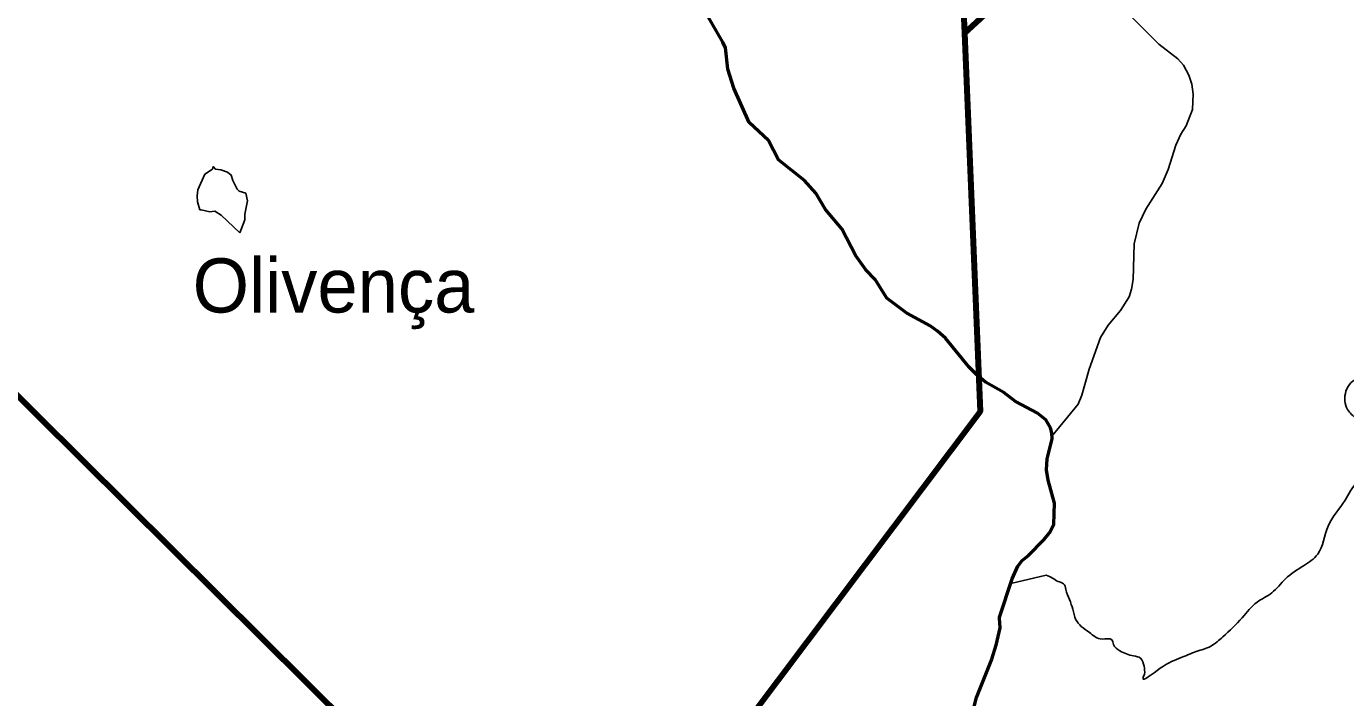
# Model space of a CAD drawing. Extents: x 553962 to 842807, y 8883888 to 9032388.
# Drawn here: x 696848 to 709028, y 8942741 to 8948937 of the extents above; entities that cross this region are included whole.
import ezdxf

# ---------------------------------------------------------------- set-up
doc = ezdxf.new("R2010")
doc.units = 0
doc.header["$LTSCALE"] = 200
for name, color, linetype, lineweight in [('21', 7, 'Continuous', 25), ('24', 7, 'Continuous', 25), ('9', 7, 'Continuous', 90)]:
    doc.layers.add(name, color=color, linetype=linetype, lineweight=lineweight)
doc.layers.add('41', color=7, linetype='Continuous')

msp = doc.modelspace()

# ---------------------------------------------------------------- linework, layer by layer
at = {"layer": '21'}
for points in [[(698875, 8947397.9), (698811.7, 8947415.6), (698794.2, 8947433.6), (698754.7, 8947514.3), (698737.5, 8947564.1), (698706.2, 8947592.7), (698643, 8947613), (698593.3, 8947619.9), (698571.6, 8947643.2), (698565.2, 8947619.3), (698494.7, 8947572.1), (698431.7, 8947429.7), (698426.6, 8947373.4), (698428.3, 8947318.5), (698449.3, 8947244.8)], [(698819.7, 8947032.6), (698863.9, 8947152.1), (698866.6, 8947202.8), (698888.3, 8947328.1), (698875, 8947397.9)], [(698449.3, 8947244.8), (698461.1, 8947244.4), (698543.5, 8947225.9), (698588, 8947231.3), (698646.7, 8947194.3), (698819.7, 8947032.6)]]:
    msp.add_lwpolyline(points, dxfattribs=at)
at = {"layer": '24'}
msp.add_line((706264.7, 8943870.5), (705937.8, 8943795.8), dxfattribs=at)
at = {"layer": '24', "lineweight": 53}
for points in [[(705832.8, 8943474.1), (705832.2, 8943483.4), (705948.7, 8943839), (706001.1, 8943954.5), (706040.2, 8944007.2), (706100.5, 8944053.4), (706243.1, 8944196.5), (706294.6, 8944261.8), (706335.3, 8944339.1), (706341.1, 8944535.4), (706282.4, 8944747.1), (706266.1, 8944843.4), (706272.3, 8944945.6), (706319.3, 8945130.2), (706317, 8945185.3), (706304, 8945230.7), (706260.8, 8945306.2), (706182.6, 8945367.1), (705978.7, 8945474.4), (705872.5, 8945557.9), (705704.5, 8945652.5), (705622.4, 8945719.5), (705553.2, 8945790.5), (705334.1, 8946058.7), (705261.1, 8946123.8), (705190.9, 8946173.3), (704977.8, 8946288.6), (704792.6, 8946429), (704685.4, 8946600), (704597.4, 8946688.7), (704507.1, 8946819.4), (704375.5, 8947069.7), (704224.8, 8947248.3), (704136.7, 8947399.1), (704032, 8947515), (703791.7, 8947704), (703699.7, 8947883.2), (703521.3, 8948048.6), (703380.4, 8948367.8), (703323, 8948543.7), (703301.3, 8948739.4), (703276.6, 8948792.4), (703126.8, 8949051.7)], [(705588.8, 8942621.5), (705620.6, 8942742.3), (705760.4, 8943097.5), (705802.3, 8943224.2), (705838.5, 8943384.3), (705832.8, 8943474.1)]]:
    msp.add_lwpolyline(points, dxfattribs=at)
at = {"layer": '24'}
msp.add_lwpolyline([(706318.1, 8945157.8), (706558.5, 8945449.1), (706593.8, 8945534.1), (706659.1, 8945772.7), (706765.2, 8946065.5), (706837, 8946180.3), (706950.8, 8946315.4), (707030.1, 8946442.2), (707051.3, 8946511.7), (707065.5, 8946600.1), (707074.4, 8946928.9), (707120.5, 8947121.8), (707182.7, 8947250.3), (707335.4, 8947487.7), (707390.2, 8947616.9), (707459.2, 8947840.2), (707507, 8947940.8), (707556.4, 8948018.2), (707613.4, 8948168.5), (707621.6, 8948310.7), (707609.1, 8948405.1), (707580.3, 8948486.2), (707531.2, 8948578), (707480.2, 8948638.3), (707302.3, 8948774), (707005.5, 8949071.8)], dxfattribs=at)
msp.add_spline([(709176.7, 8946925.6), (709156.7, 8946869.4), (709176.7, 8946841.3), (709216.8, 8946793.2), (709212.8, 8946737.1), (709184.8, 8946692.9), (709188.8, 8946588.6), (709228.9, 8946464.3), (709269, 8946420.2), (709348.3, 8946367.6), (709278.6, 8946282.4), (709255.4, 8946174.1), (709332.8, 8946019.3), (709379.2, 8945910.9), (709356, 8945833.6), (709270.9, 8945740.7), (709077.4, 8945647.8), (709031, 8945570.4), (709046.4, 8945400.2), (709123.8, 8945315), (709232.2, 8945144.8), (709286.4, 8944990), (709270.9, 8944866.1), (709131.6, 8944726.8), (709023.2, 8944564.3), (708866.1, 8944324.4), (708770.1, 8944064.3), (708640.1, 8943959.1), (708473, 8943838.3), (708346, 8943708.3), (708209.8, 8943621.6), (708073.6, 8943479.2), (707894, 8943302.8), (707782.6, 8943216.1), (707649.5, 8943166.6), (707510.2, 8943110.8), (707315.1, 8943011.8), (707157.2, 8942922), (707169.6, 8942959.1), (707166.5, 8943030.3), (707135.6, 8943104.6), (707070.6, 8943126.3), (706943.7, 8943172.8), (706884.8, 8943231.6), (706869.3, 8943274.9), (706779.6, 8943281.1), (706661.9, 8943343), (706587.6, 8943398.7), (706538.1, 8943460.7), (706510.2, 8943556.6), (706445.2, 8943739.3), (706423.6, 8943791.9), (706374, 8943813.6), (706321.4, 8943844.5), (706264.7, 8943870.5)], degree=3, dxfattribs=at)
at = {"layer": '9'}
for points in [[(705081.2, 8958366.8), (705509.2, 8948874.2), (720755.9, 8962863.6), (723053.6, 8963740.6)], [(705509.2, 8948874.2), (705653.5, 8945380.8), (701918.9, 8940415.3), (694874, 8947402.7)]]:
    msp.add_lwpolyline(points, dxfattribs=at)

# ---------------------------------------------------------------- texts
at = {"layer": '41'}
msp.add_text('Olivença', height=500, dxfattribs=at).set_placement((698383.7, 8946295.8))

doc.saveas('drawing.dxf')
